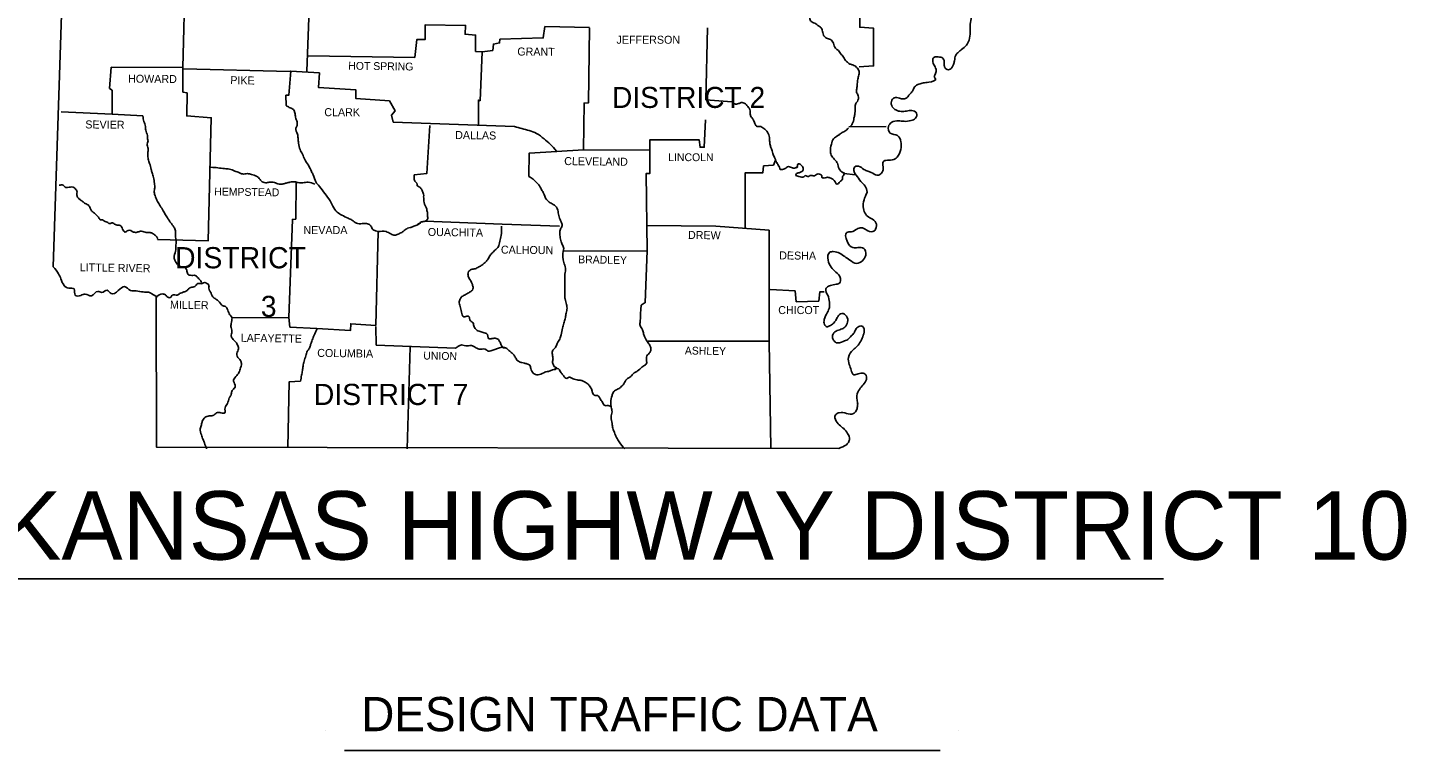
# Model space of a CAD drawing. Extents: x 166 to 3406, y 71 to 2074.
# Drawn here: x 2681 to 3406, y 1249 to 1629 of the extents above; entities that cross this region are included whole.
import ezdxf

# ---------------------------------------------------------------- set-up
doc = ezdxf.new("R2010")
doc.units = 0
for name, color, linetype in [('1', 7, 'Continuous'), ('2', 7, 'Continuous'), ('3', 7, 'Continuous')]:
    doc.layers.add(name, color=color, linetype=linetype)

msp = doc.modelspace()

# ---------------------------------------------------------------- linework, layer by layer
at = {"layer": '1'}
for p, q in [((3112.81, 1577.02), (3132.37, 1577.31)), ((2592.35, 1339.32), (3278.08, 1339.32)), ((2837.84, 1259.83), (2837.84, 1259.83)), ((3170.5, 1259.83), (3170.5, 1259.83)), ((2847.67, 1249.11), (3160.76, 1249.11))]:
    msp.add_line(p, q, dxfattribs=at)
for points in [[(2683.09, 1931.5), (2703.34, 1768.89), (2694.54, 1503.44)], [(3118.09, 1608.62), (3125.72, 1609.11), (3125.62, 1628.97), (3118.48, 1629.46), (3118.87, 1668.31), (3112.71, 1669.19), (3112.51, 1695.31), (3195.97, 1695.9)], [(2830.14, 1667.23), (2827.89, 1606.28)], [(2763.81, 1656.47), (2762.73, 1608.33), (2725.06, 1608.43), (2724.18, 1597.27), (2725.55, 1596.3), (2725.45, 1583.77), (2698.74, 1584.95)], [(2828.58, 1614.4), (2884.54, 1613.61), (2885.62, 1622.91), (2890.02, 1622.91), (2890.12, 1630.74), (2911.25, 1630.44), (2911.06, 1625.75), (2916.54, 1625.35), (2916.54, 1616.74), (2920.06, 1616.45)], [(2920.06, 1616.45), (2925.54, 1617.23), (2925.93, 1620.56), (2929.16, 1621.15), (2929.35, 1623.1), (2952.15, 1623.79), (2953.03, 1629.76), (2976.42, 1629.37)], [(2976.42, 1629.17), (2975.83, 1589.64), (2973.58, 1589.54), (2973.29, 1564.99)], [(3038.45, 1629.07), (3037.66, 1591.21), (3051.26, 1590.13)], [(2920.06, 1616.45), (2918.89, 1590.82), (2918.01, 1591.11), (2918.1, 1577.8)], [(2762.73, 1608.33), (2762.73, 1595.32), (2764.88, 1594.93), (2764.69, 1582.79), (2777.6, 1581.82), (2776.04, 1517.14), (2749.43, 1517.83)], [(2762.93, 1607.65), (2818.89, 1606.18)], [(2817.03, 1588.27), (2816.84, 1593.65), (2818.4, 1593.75), (2819.38, 1606.37), (2834.45, 1605.39), (2834.06, 1597.67), (2853.53, 1596.59), (2853.63, 1591.89), (2871.24, 1590.82), (2874.27, 1585.53), (2872.41, 1583.18), (2873.29, 1579.56), (2937.08, 1577.22)], [(2725.45, 1583.77), (2741.7, 1582.79)], [(3037.37, 1580.74), (3036.78, 1566.36), (3034.53, 1566.36), (3034.14, 1570.17), (3008.12, 1570.17), (3008.12, 1564.69)], [(2892.47, 1577.71), (2891, 1552.56), (2884.25, 1551.78)], [(2959.2, 1564.11), (2944.72, 1563.23), (2944.62, 1551)], [(2973.29, 1564.99), (2959, 1564.11)], [(2973.29, 1564.99), (3007.92, 1564.79)], [(3008.12, 1564.79), (3008.21, 1552.56), (3006.16, 1552.46), (3006.75, 1511.86)], [(3074.26, 1559.61), (3073.08, 1556.96), (3067.9, 1556.47), (3067.6, 1552.95), (3058.31, 1552.95), (3058.21, 1523.7)], [(3085.22, 1555.3), (3085.51, 1555.59), (3085.8, 1555.89), (3085.8, 1555.89)], [(2822.22, 1548.06), (2822.02, 1528.59), (2820.26, 1528.39), (2818.31, 1476.83)], [(2890.02, 1527.42), (2930.53, 1525.95), (2960.57, 1524.77)], [(3006.45, 1525.17), (3042.75, 1524.87), (3070.93, 1522.72)], [(3070.93, 1522.72), (3070.93, 1464.21), (3071.71, 1407.95)], [(2865.37, 1521.94), (2864.1, 1472.63), (2850.89, 1473.51), (2850.79, 1469.89), (2833.18, 1470.96)], [(2962.52, 1511.76), (3006.75, 1511.86)], [(3006.75, 1511.86), (3005.77, 1484.66), (3003.62, 1483.29)], [(2748.64, 1487.69), (2748.84, 1408.54), (3107.42, 1407.95)], [(3071.42, 1491.51), (3084.53, 1490.73), (3085.12, 1485.05), (3096.96, 1485.44), (3097.45, 1490.24), (3099.7, 1490.24)], [(2833.18, 1470.96), (2818.99, 1471.74), (2818.31, 1476.83), (2788.66, 1476.54)], [(2906.07, 1460.69), (2864.29, 1462.25), (2864.1, 1472.14)], [(3007.33, 1464.31), (3070.93, 1464.31)], [(2882.1, 1461.37), (2880.53, 1407.66)], [(2824.57, 1443.27), (2818.5, 1442.88), (2817.82, 1408.44)]]:
    msp.add_lwpolyline(points, dxfattribs=at)
for points in [[(3189.81, 1672.22), (3187.56, 1669.38), (3184.23, 1671.14), (3184.23, 1673.49), (3184.72, 1675.94), (3183.55, 1677.5), (3181.49, 1676.82), (3181.49, 1673.79), (3181.29, 1670.85), (3180.71, 1666.64), (3182.08, 1665.37), (3185.21, 1664.98), (3187.46, 1664.39), (3188.83, 1662.14), (3188.73, 1659.4), (3187.65, 1656.76), (3186.09, 1654.61), (3183.64, 1653.83), (3181.69, 1655.1), (3180.9, 1657.64), (3180.02, 1659.89), (3178.36, 1661.56), (3176.6, 1659.7), (3176.21, 1656.27), (3176.3, 1653.34), (3176.3, 1649.33), (3178.85, 1646.68), (3180.41, 1643.65), (3179.92, 1640.91), (3178.07, 1637.68), (3177.28, 1634.84), (3176.5, 1631.03), (3176.6, 1626.82), (3175.91, 1622.71), (3174.54, 1619.97), (3172, 1617.72), (3170.34, 1616.26), (3168.97, 1614.79), (3168.28, 1611.85), (3167.79, 1609.8), (3165.93, 1607.35), (3164.47, 1607.16), (3163.29, 1608.13), (3162.9, 1609.8), (3162.9, 1611.46), (3162.12, 1613.12), (3159.67, 1613.81), (3157.72, 1613.71), (3156.83, 1612.34), (3158.11, 1608.53), (3158.6, 1606.08), (3157.91, 1602.75), (3158.3, 1602.36), (3154.78, 1600.5), (3151.94, 1600.21), (3149.59, 1599.52), (3147.34, 1598.06), (3146.27, 1595.9), (3144.7, 1594.14), (3143.33, 1592.48), (3141.47, 1591.7), (3139.42, 1592.09), (3136.68, 1592.38), (3135.11, 1590.43), (3135.6, 1587.59), (3137.46, 1585.92), (3140.2, 1585.14), (3143.04, 1585.34), (3145.78, 1585.63), (3148.32, 1584.26), (3147.83, 1581.62), (3145.39, 1580.35), (3141.77, 1579.96), (3138.83, 1580.25), (3135.31, 1579.47), (3133.55, 1577.22), (3134.53, 1573.79), (3138.34, 1572.42), (3140.1, 1569.19), (3140.2, 1566.16), (3138.93, 1562.15), (3137.17, 1560.29), (3133.74, 1559.51), (3131.1, 1559.02), (3130.71, 1554.52), (3129.54, 1552.27), (3127.48, 1551.58), (3124.55, 1553.05), (3122.79, 1553.73), (3120.63, 1554.71), (3117.89, 1556.38), (3115.84, 1556.08), (3116.43, 1551.78), (3116.62, 1551.58), (3118.97, 1548.35), (3121.32, 1545.81), (3122.39, 1542.78)], [(3088.44, 1640.72), (3088.74, 1636.7), (3091.09, 1636.12), (3092.06, 1635.04), (3092.55, 1632.79), (3094.22, 1631.81), (3096.47, 1630.44), (3097.84, 1629.46), (3098.81, 1627.9), (3099.4, 1625.35), (3100.97, 1623.69), (3103.12, 1622.91), (3104.69, 1621.05), (3105.66, 1618.41), (3107.23, 1617.23), (3108.79, 1615.18), (3109.58, 1614.3), (3110.95, 1611.95), (3112.32, 1610.78), (3113.3, 1610.09), (3114.86, 1609.6), (3116.82, 1608.33), (3118.09, 1606.37), (3118.09, 1604.91), (3117.6, 1602.66), (3117.21, 1600.31), (3117.01, 1597.67), (3116.82, 1595.32), (3117.7, 1593.36), (3117.21, 1590.43), (3116.23, 1588.86), (3116.13, 1586.71), (3115.84, 1583.48), (3115.45, 1581.62), (3114.57, 1578.59), (3113.3, 1577.02)], [(2817.03, 1588.27), (2818.6, 1587.29), (2820.46, 1586.41), (2821.44, 1584.95), (2821.83, 1582.7), (2822.51, 1580.25), (2822.71, 1577.71), (2822.12, 1576.34), (2822.9, 1573.21), (2823.2, 1571.05), (2823.49, 1568.51), (2824.27, 1565.08), (2825.55, 1562.74), (2826.72, 1559.9), (2828.68, 1556.87), (2830.34, 1553.54), (2831.12, 1551.78), (2832.59, 1548.16), (2834.45, 1545.71), (2837.38, 1541.99), (2840.03, 1538.18), (2841.49, 1535.34), (2843.74, 1532.21), (2846.29, 1530.64), (2849.52, 1528.98), (2851.57, 1528), (2853.92, 1526.34), (2856.95, 1526.14), (2859.2, 1526.14), (2861.26, 1525.26), (2862.24, 1523.5), (2864, 1522.33), (2865.37, 1521.94)], [(3051.26, 1590.13), (3052.73, 1589.15), (3054.79, 1589.25), (3056.16, 1589.84), (3057.23, 1589.74), (3058.7, 1588.86), (3059.68, 1587.69), (3060.36, 1586.81), (3060.85, 1585.44), (3060.85, 1584.16), (3061.34, 1582.4), (3061.93, 1581.72), (3062.71, 1580.45), (3063.2, 1579.27), (3063.49, 1578.49), (3064.57, 1577.22), (3065.55, 1577.31), (3066.43, 1577.22), (3067.6, 1576.53), (3069.36, 1575.16), (3069.66, 1574.77), (3070.83, 1572.23), (3071.03, 1570.66), (3071.22, 1568.61), (3071.62, 1566.65), (3072.4, 1564.5), (3072.79, 1563.03), (3073.67, 1560.98), (3074.26, 1559.61), (3075.04, 1557.84), (3076.21, 1555.89), (3076.7, 1554.71), (3078.37, 1554.81), (3079.54, 1555.3), (3080.42, 1556.08), (3081.5, 1555.99), (3082.67, 1555.59), (3084.24, 1555.3), (3085.22, 1555.89), (3085.7, 1556.28), (3085.8, 1557.16), (3086.68, 1557.65), (3087.66, 1556.96), (3088.74, 1555.4), (3088.74, 1554.42), (3088.35, 1553.83), (3087.07, 1553.05), (3085.31, 1552.46), (3084.82, 1551.78), (3086.49, 1551), (3089.13, 1550.8), (3089.81, 1551.39), (3091.57, 1550.9), (3092.26, 1551.39), (3094.61, 1551.29), (3095.68, 1552.07), (3097.84, 1551.97), (3098.52, 1551.48), (3098.52, 1550.6), (3100.28, 1550.21), (3101.55, 1550.51), (3103.22, 1550.02), (3104.69, 1549.23), (3105.47, 1548.16), (3106.45, 1546.98), (3107.33, 1547.28), (3108.01, 1548.16), (3109.48, 1549.72), (3109.48, 1550.7), (3109.87, 1551.39), (3110.36, 1552.37)], [(2741.7, 1582.79), (2742.19, 1579.86), (2743.07, 1577.31), (2743.16, 1575.36), (2744.04, 1572.42), (2744.04, 1571.35), (2744.34, 1569.19), (2743.95, 1568.02), (2744.44, 1565.67), (2744.34, 1563.91), (2744.34, 1562.44), (2744.44, 1560), (2745.22, 1557.84), (2746, 1554.62), (2746.49, 1552.95), (2747.27, 1550.41), (2747.76, 1547.28), (2747.86, 1544.93), (2747.66, 1542.78), (2748.25, 1540.33), (2749.33, 1537.88), (2750.7, 1535.54), (2752.36, 1532.89), (2753.54, 1530.84), (2755, 1528.59), (2756.18, 1526.73), (2757.94, 1524.38), (2758.72, 1522.43), (2758.72, 1519.69), (2759.11, 1517.14), (2759.01, 1514.31), (2758.82, 1511.76), (2758.13, 1508.24), (2758.62, 1506.58), (2760.48, 1504.13), (2761.66, 1503.44), (2763.71, 1503.05), (2764.69, 1501.68), (2765.28, 1499.63), (2767.33, 1498.94), (2769.58, 1498.75), (2770.66, 1497.57), (2772.12, 1496.01), (2772.61, 1495.23)], [(2937.08, 1577.22), (2944.72, 1575.06), (2948.63, 1573.6), (2952.54, 1570.76), (2955.77, 1567.92), (2959, 1564.3)], [(3112.61, 1576.43), (3110.56, 1574.77), (3108.79, 1573.79), (3106.94, 1572.42), (3104.69, 1570.76), (3103.61, 1567.92), (3103.02, 1564.01), (3103.8, 1561.66), (3105.57, 1559.61), (3106.74, 1557.94), (3107.62, 1555.01), (3109.77, 1552.95), (3110.46, 1552.66)], [(2777.41, 1555.79), (2781.13, 1555.5), (2784.55, 1555.1), (2787.19, 1554.81), (2789.93, 1553.83), (2792.38, 1552.95), (2793.94, 1552.27), (2796.59, 1552.46), (2798.84, 1551.97), (2801.38, 1551.09), (2803.24, 1549.43), (2804.41, 1548.16), (2806.66, 1547.67), (2808.52, 1547.96), (2810.77, 1547.77), (2813.32, 1546.98), (2815.37, 1547.08), (2817.03, 1547.47), (2818.99, 1547.96), (2821.44, 1548.16), (2823.3, 1547.77), (2825.74, 1547.67), (2828.58, 1547.96), (2832.1, 1546.98)], [(2884.25, 1551.78), (2884.25, 1549.92), (2884.94, 1548.16), (2885.62, 1547.38), (2885.91, 1546.1), (2886.79, 1545.52), (2888.07, 1544.34), (2888.75, 1542.68), (2889.24, 1541.6), (2889.24, 1540.23), (2889.34, 1538.86), (2889.53, 1537.2), (2890.71, 1534.26), (2891, 1533.09), (2891.2, 1532.11), (2891.29, 1530.45), (2891.29, 1528.49), (2890.02, 1527.42)], [(2697.57, 1546.3), (2699.72, 1546.4), (2701.19, 1545.12), (2702.07, 1545.22), (2703.64, 1545.42), (2705.1, 1545.32), (2706.18, 1544.44), (2707.06, 1542.87), (2706.96, 1541.41), (2707.06, 1540.82), (2707.75, 1539.55), (2708.92, 1538.57), (2710.19, 1537.59), (2711.37, 1536.81), (2713.32, 1535.54), (2713.52, 1535.15), (2714.3, 1533.58), (2715.28, 1532.31), (2716.45, 1531.53), (2717.73, 1530.16), (2718.31, 1529.57), (2719.29, 1528.2), (2720.37, 1528.1), (2721.83, 1527.22), (2722.91, 1526.93), (2724.09, 1526.14), (2725.26, 1526.54), (2726.73, 1525.95), (2728.68, 1525.36), (2729.76, 1525.17), (2731.03, 1523.31), (2732.3, 1521.74), (2733.87, 1522.62), (2736.8, 1521.74), (2738.66, 1521.64), (2740.33, 1522.13), (2741.6, 1522.03), (2743.95, 1521.45), (2745.41, 1521.45), (2746.98, 1520.86), (2748.45, 1519.69), (2749.43, 1518.41), (2749.43, 1517.83)], [(2944.62, 1551), (2946.87, 1549.53), (2948.73, 1547.57), (2950.1, 1546.1), (2950.98, 1544.44), (2952.15, 1542.48), (2953.82, 1538.77), (2955.28, 1537.49), (2957.34, 1536.22), (2958.61, 1535.34), (2959.88, 1532.5), (2960.47, 1529.67), (2961.54, 1527.12), (2962.03, 1525.17), (2961.15, 1523.21), (2960.96, 1519.3), (2961.54, 1516.65), (2962.33, 1514.7), (2962.82, 1512.45), (2962.52, 1511.76)], [(3122.39, 1542.78), (3121.42, 1540.53), (3120.34, 1536.61), (3120.63, 1533.29), (3122.1, 1530.45), (3124.45, 1528.88), (3126.99, 1526.63), (3126.8, 1523.21), (3125.33, 1521.94), (3121.91, 1522.82), (3119.26, 1523.99), (3117.01, 1523.31), (3113.98, 1521.84), (3111.73, 1521.55), (3111.83, 1516.85), (3114.86, 1513.52), (3117.5, 1513.52), (3120.54, 1513.13), (3121.61, 1509.61), (3119.85, 1506.67), (3116.92, 1505.21), (3113.2, 1506.97), (3110.56, 1508.83), (3107.91, 1510.59), (3104.59, 1511.47), (3102.73, 1511.08), (3101.85, 1506.97), (3103.41, 1503.25), (3105.96, 1500.71), (3108.31, 1497.38), (3107.91, 1494.93), (3106.15, 1494.25), (3103.02, 1493.56), (3101.16, 1492.58), (3100.67, 1491.8), (3101.65, 1488.48), (3102.53, 1484.86), (3102.53, 1482.12), (3101.46, 1479.57), (3099.79, 1475.66), (3099.99, 1473.11), (3101.16, 1471.94), (3102.63, 1472.33), (3104.59, 1473.7), (3105.86, 1475.27), (3106.94, 1477.22), (3108.99, 1478.89), (3111.53, 1477.42), (3112.12, 1474.39), (3110.65, 1471.74), (3108.6, 1470.57), (3106.06, 1469.59), (3104.2, 1467.44), (3104.69, 1464.9), (3106.15, 1463.53), (3109.77, 1464.21), (3112.22, 1465.29), (3113.59, 1466.66), (3115.25, 1468.32), (3116.13, 1469.98), (3117.4, 1471.74), (3119.66, 1472.23), (3120.73, 1470.77), (3120.34, 1467.44), (3118.97, 1464.31), (3117.11, 1461.67), (3115.06, 1459.81), (3112.51, 1455.8), (3113, 1452.08), (3113.98, 1449.05), (3115.35, 1446.7), (3117.7, 1447.19), (3120.34, 1447.48), (3121.91, 1446.21), (3121.71, 1443.47), (3119.75, 1440.83), (3117.89, 1438.28), (3116.92, 1434.76), (3117.31, 1432.31), (3117.31, 1430.06), (3116.52, 1427.62), (3115.15, 1426.25), (3111.53, 1426.35), (3107.72, 1426.74), (3105.66, 1425.56), (3106.06, 1422.24), (3108.31, 1419.79), (3109.87, 1418.52), (3112.12, 1415.78), (3113.1, 1413.53), (3112.81, 1411.57), (3111.44, 1409.91), (3107.42, 1407.95)], [(2888.16, 1527.02), (2885.62, 1525.36), (2883.66, 1524.58), (2882.2, 1524.09), (2880.83, 1523.7), (2879.06, 1522.52), (2877.7, 1521.55), (2875.84, 1520.66), (2874.07, 1520.08), (2871.92, 1520.76), (2870.75, 1521.45), (2869.48, 1521.94), (2865.37, 1521.94)], [(2885.62, 1525.36), (2888.16, 1527.02), (2890.02, 1527.42)], [(2930.14, 1524.77), (2929.94, 1519.88), (2929.26, 1516.85), (2928.57, 1514.11), (2927.1, 1512.54), (2925.54, 1510.98), (2924.07, 1509.22), (2922.8, 1507.06), (2921.53, 1505.7), (2919.86, 1504.33), (2918.2, 1503.35), (2916.34, 1502.47), (2914.29, 1501.98), (2912.82, 1500.9), (2912.72, 1498.55), (2914.39, 1495.23), (2914.97, 1493.66), (2915.17, 1491.8), (2914.48, 1490.73), (2912.92, 1489.84), (2911.06, 1488.77), (2909.4, 1487.79), (2908.22, 1486.13), (2908.03, 1483.88), (2908.81, 1481.24), (2909.1, 1479.67), (2910.37, 1477.22), (2911.35, 1477.32), (2913.11, 1477.22), (2913.31, 1476.73), (2913.41, 1476.25), (2913.8, 1474.97), (2915.27, 1473.9), (2915.46, 1472.92), (2916.34, 1471.06), (2917.81, 1469.79), (2918.89, 1469.4), (2921.14, 1468.71), (2922.31, 1468.42), (2923.58, 1465.58), (2925.15, 1465.68), (2926.32, 1465.87), (2928.28, 1465.38), (2929.16, 1464.21), (2930.04, 1462.25), (2931.21, 1460.88), (2932, 1460.88)], [(2962.52, 1511.76), (2962.91, 1505.7), (2963.79, 1502.76), (2963.5, 1499.63), (2963.4, 1496.6), (2963.4, 1493.86), (2963.4, 1491.21), (2963.4, 1488.48), (2963.6, 1486.52), (2964.28, 1483.68), (2964.58, 1481.04), (2963.99, 1478.5), (2963.7, 1476.15), (2962.91, 1473.8), (2962.23, 1471.16), (2961.45, 1467.73), (2960.76, 1465.48), (2959.39, 1463.13), (2958.51, 1460.98), (2957.14, 1459.61), (2956.95, 1457.26), (2957.24, 1455.11), (2957.04, 1453.15), (2957.73, 1451.3), (2959.49, 1450.02)], [(2694.54, 1503.44), (2697.37, 1499.73), (2698.55, 1497.09), (2700.21, 1493.66), (2702.66, 1492.29), (2705.5, 1491.8), (2706.08, 1488.48), (2709.02, 1488.38), (2711.37, 1489.06), (2714.59, 1488.18), (2718.02, 1490.53), (2719.98, 1489.94), (2722.81, 1491.12), (2724.97, 1489.36), (2728.68, 1490.92), (2732.01, 1493.07), (2735.14, 1491.02), (2738.17, 1490.73), (2741.79, 1490.24), (2744.63, 1490.04), (2747.18, 1488.77), (2749.03, 1487.5), (2748.64, 1487.69)], [(2748.64, 1487.69), (2752.07, 1489.16), (2753.54, 1488.67), (2754.81, 1487.4), (2756.27, 1487.4), (2757.06, 1488.57), (2758.53, 1488.67), (2759.7, 1488.57), (2760.97, 1489.36), (2762.05, 1489.84), (2763.51, 1490.33), (2764.59, 1490.73), (2765.57, 1491.8), (2767.33, 1492.68), (2769.39, 1493.37), (2769.97, 1494.35), (2770.95, 1494.74), (2772.91, 1494.64), (2774.18, 1495.23), (2775.26, 1494.74), (2776.23, 1494.05), (2776.43, 1491.51), (2777.21, 1490.14), (2778.39, 1487.69), (2780.05, 1486.42), (2781.62, 1485.15), (2782.2, 1484.37), (2783.87, 1482.9), (2785.33, 1482.41), (2786.02, 1481.33), (2787.09, 1478.79), (2788.66, 1476.54)], [(3003.62, 1483.29), (3003.32, 1480.26), (3003.22, 1477.42), (3003.03, 1474.68), (3003.03, 1472.63), (3004.2, 1470.37), (3004.89, 1468.22), (3005.57, 1466.36), (3006.94, 1463.92), (3008.21, 1462.06), (3008.61, 1459.42), (3007.82, 1458.05), (3006.36, 1455.99), (3006.26, 1452.27), (3004.5, 1451.1), (3002.25, 1449.14), (3000.97, 1448.26), (2999.6, 1447.38), (2998.14, 1445.82), (2995.98, 1444.35), (2994.42, 1441.9), (2992.66, 1440.04), (2991.19, 1439.07), (2989.14, 1437.79), (2988.26, 1435.84), (2987.57, 1432.22), (2987.86, 1429.58), (2988.26, 1427.23), (2987.77, 1424.29), (2988.26, 1421.06), (2988.74, 1418.52), (2989.53, 1416.27), (2990.6, 1413.72), (2991.97, 1411.38), (2994.91, 1407.76)], [(2788.66, 1476.54), (2788.07, 1473.7), (2787.98, 1471.45), (2788.46, 1468.81), (2787.98, 1467.54), (2788.76, 1465.68), (2790.23, 1464.21), (2791.3, 1462.65), (2791.99, 1460.39), (2791.11, 1457.85), (2792.08, 1455.21), (2792.97, 1454.23), (2793.45, 1452.67), (2792.77, 1449.63), (2791.89, 1447.38), (2789.93, 1445.13), (2789.34, 1444.06), (2789.64, 1442.59), (2790.13, 1440.24), (2789.64, 1439.55), (2788.37, 1437.89), (2787.98, 1436.03), (2787.09, 1434.47), (2786.12, 1431.63), (2784.84, 1429.28), (2784.65, 1426.64), (2782.69, 1426.64), (2780.44, 1426.64), (2778.39, 1425.17), (2776.53, 1425.07), (2774.28, 1424.19), (2772.91, 1422.33), (2772.42, 1420.28), (2771.83, 1418.32), (2772.42, 1415), (2773.3, 1412.65), (2773.98, 1410.79), (2775.16, 1407.76)], [(2824.57, 1443.27), (2825.06, 1446.4), (2825.55, 1448.85), (2825.84, 1451.2), (2826.43, 1453.84), (2827.31, 1456.68), (2828.09, 1459.03), (2829.17, 1460.69), (2829.85, 1462.65), (2830.73, 1464.99), (2831.61, 1467.44), (2833.18, 1470.57)], [(2906.07, 1460.69), (2907.63, 1461.76), (2909.1, 1462.35), (2910.57, 1462.06), (2912.13, 1461.86), (2913.5, 1462.06), (2915.27, 1461.76), (2916.73, 1460.88), (2918.4, 1460.2), (2920.06, 1460.2), (2921.53, 1460.2), (2922.8, 1459.32), (2925.15, 1459.42), (2927.1, 1460.2), (2929.06, 1460.79), (2931.7, 1461.08), (2934.05, 1459.42), (2935.71, 1458.05), (2937.08, 1456.48), (2938.06, 1454.72), (2939.14, 1453.74), (2940.9, 1453.06), (2942.27, 1452.76), (2943.93, 1452.27), (2944.81, 1451.88), (2945.6, 1450.02), (2946.87, 1447.48), (2949.31, 1446.6), (2952.35, 1447.77), (2954.79, 1448.46), (2956.55, 1449.05), (2957.63, 1449.44), (2958.61, 1449.53), (2958.32, 1449.73), (2959.49, 1450.02), (2960.57, 1449.24), (2961.25, 1448.16), (2962.43, 1446.6), (2963.5, 1445.23), (2964.58, 1444.74), (2965.65, 1445.33), (2967.12, 1444.84), (2968.39, 1444.35), (2969.86, 1443.96), (2971.13, 1443.86), (2972.8, 1443.47), (2974.07, 1442.78), (2975.24, 1442.1), (2976.42, 1440.83), (2977.59, 1438.87), (2977.98, 1437.3), (2979.35, 1435.74), (2980.62, 1435.74), (2982.48, 1433.2), (2983.17, 1432.22), (2984.63, 1430.46), (2985.71, 1430.46), (2987.77, 1430.06)]]:
    msp.add_spline(points, degree=3, dxfattribs=at)
at = {"layer": '3'}
msp.add_line((3110.16, 1552.56), (3116.33, 1551.78), dxfattribs=at)

# ---------------------------------------------------------------- texts
at = {"layer": '1'}
msp.add_text('DESIGN TRAFFIC DATA', height=18, dxfattribs=at).set_placement((2856.47, 1259.23))
at = {"layer": '2'}
for s, height, p in [('JEFFERSON', 4.207, (2990.6, 1620.76)), ('CLARK', 4.207, (2837.01, 1582.67)), ('LINCOLN', 4.109, (3017.8, 1559.02)), ('NEVADA', 4.207, (2826.04, 1520.66)), ('CHICOT', 4.207, (3075.63, 1478.59)), ('ARKANSAS HIGHWAY DISTRICT 10', 36, (2599.88, 1349.45))]:
    msp.add_text(s, height=height, dxfattribs=at).set_placement(p)
for s, height, rotation, p in [('GRANT', 4.207, 359.40319, (2938.45, 1614.59)), ('HOT SPRING', 4.109, 359.22157, (2849.61, 1607.16)), ('HOWARD', 4.207, 359.51446, (2733.87, 1600.31)), ('PIKE', 4.206, 359.04516, (2787.58, 1599.52)), ('SEVIER', 4.207, 359.42706, (2711.37, 1576.24)), ('DALLAS', 4.206, 359.24615, (2905.78, 1570.66)), ('CLEVELAND', 4.207, 359.33765, (2963.11, 1556.96)), ('HEMPSTEAD', 4.108, 359.1885, (2779.17, 1541.02)), ('OUACHITA', 4.207, 359.20428, (2891.39, 1519.69)), ('DREW', 4.206, 359.22578, (3028.17, 1518.12)), ('CALHOUN', 4.207, 359.36341, (2929.84, 1510.39)), ('BRADLEY', 4.108, 359.1449, (2970.45, 1505.3)), ('DESHA', 4.206, 359.3704, (3076.12, 1507.36)), ('LITTLE RIVER', 4.2073, 359.16968, (2708.43, 1501.1)), ('MILLER', 4.206, 359.13195, (2755.88, 1481.43)), ('LAFAYETTE', 4.206, 359.18388, (2793.06, 1464.02)), ('COLUMBIA', 4.206, 359.21248, (2833.28, 1456.09)), ('UNION', 4.109, 358.95837, (2889.04, 1454.72)), ('ASHLEY', 4.109, 359.2361, (3026.51, 1457.36))]:
    msp.add_text(s, height=height, rotation=rotation, dxfattribs=at).set_placement(p)
at = {"layer": '3'}
for s, height, p in [('DISTRICT 2', 11.056, (2988.26, 1587)), ('DISTRICT', 11.154, (2758.57, 1502.65)), ('3', 11.06, (2803.68, 1477.12)), ('DISTRICT 7', 11.154, (2831.51, 1430.75))]:
    msp.add_text(s, height=height, dxfattribs=at).set_placement(p)

doc.saveas('drawing.dxf')
